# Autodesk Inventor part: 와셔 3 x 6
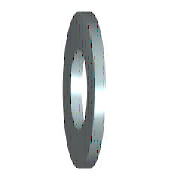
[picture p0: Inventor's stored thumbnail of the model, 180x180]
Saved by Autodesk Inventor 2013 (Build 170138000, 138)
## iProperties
IsCustomPart: 0
Created: 2012-02
Part Number: 와셔 3 x 6
Material: 강철, 연강
Description: 평면 와셔
Document SubType Name: Modeling
Standard: KS B 1326
Designer: mduedu
Standards Organization: KS
Language: ko-KR
Size Designation: 3x6
Categories: <MemberInstance><Categories><Category DisplayName="조임쇠" InternalName="e4da775c-781d-43d5-af7c-5136215cf5a6" Mnemonic="FSTN"><Category DisplayName="와셔" InternalN
Density: 7.86 g/cm^3
Mass: 0.0795112 g
Surface Area: 0.54915 cm^2
Volume: 0.0101159 cm^3
Author: mduedu
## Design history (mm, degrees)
sketch "스케치"
  geometry: C1 r 3 at (0, 0); C2 r 1.6 at (0, 0); 1 further point
  constraints: 2 centre point, 2 coincident
  dimensions: "d0" = 3.2 diameter of C2 (= SD1); "d1" = 6 diameter of C1 (= SD2)
extrude "본체" new body sketch "스케치" distance "d2" = 0.5 (= SD); taper "d3" = 0 deg
workaxis "Work Axis1"
workplane "Work Plane1"
body "Solid1"
other parameters: "SD1" = 3.2 [user parameter; used in 1 equation term], "SD2" = 6 [user parameter; used in 1 equation term], "SD" = 0.5 [user parameter; used in 1 equation term], "d4" = 0, "d5" = 0, "d6" = 0, "d7" = 0, "NND" = 3 [user parameter]
